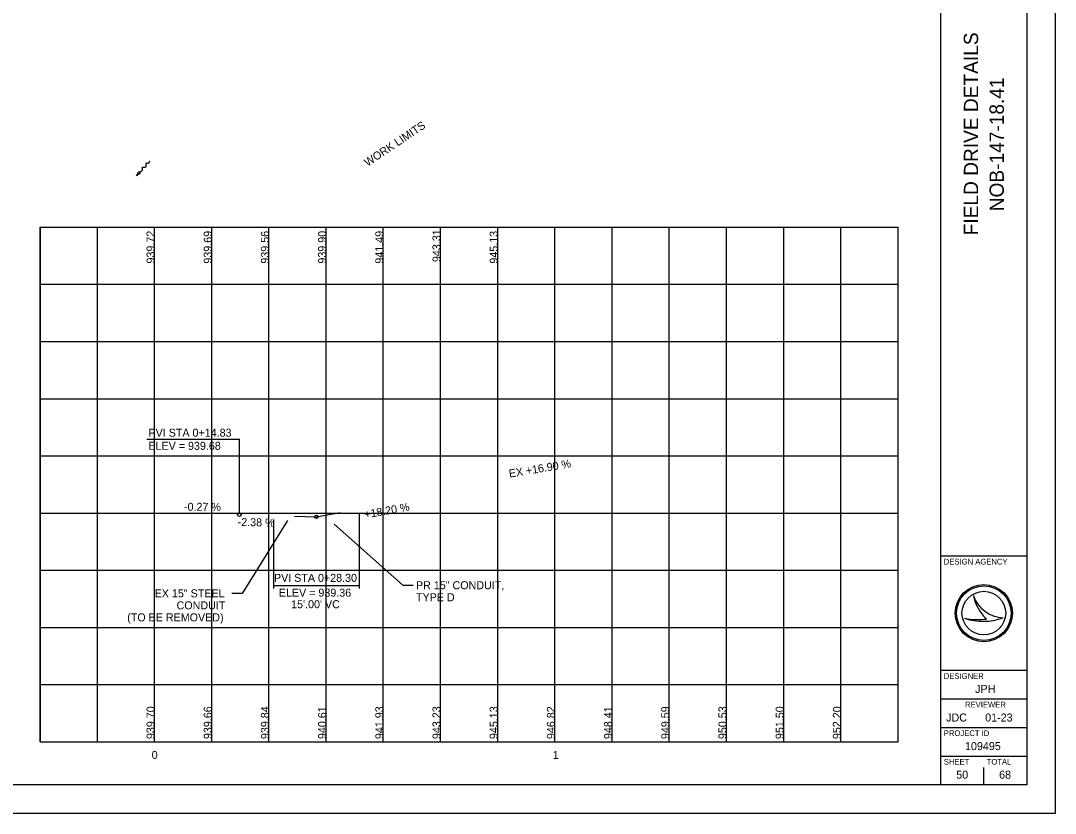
# Model space of a CAD drawing. Extents: x 1052 to 3483, y 402 to 622.
# Drawn here: x 1210.8 to 1391.7, y 401.8 to 540.4 of the extents above; entities that cross this region are included whole.
import ezdxf

# ---------------------------------------------------------------- set-up
doc = ezdxf.new("R2010")
doc.units = 0
for name, color, linetype in [('DR_P_Culvert', 7, 'Continuous'), ('DR_X_Culvert', 7, 'Continuous'), ('PF_X_Ground_Line', 7, 'Continuous'), ('RW_X_CL_100_Stations', 7, 'Continuous'), ('SC_Scratch1', 7, 'Continuous'), ('SV_X_Shot_Marker', 7, 'Continuous'), ('TX_P_1', 7, 'Continuous'), ('XS_X_Pavt', 7, 'Continuous')]:
    doc.layers.add(name, color=color, linetype=linetype)

msp = doc.modelspace()

# ---------------------------------------------------------------- linework, layer by layer
at = {"layer": 'DR_P_Culvert'}
for p, q in [((1257.45, 453.01), (1249.54, 440.25)), ((1249.54, 440.25), (1247.77, 440.25))]:
    msp.add_line(p, q, dxfattribs=at)
at = {"layer": 'DR_X_Culvert'}
for p, q in [((1214.23, 414.29), (1214.23, 504.29)), ((1224.23, 414.29), (1224.23, 504.29)), ((1234.23, 414.29), (1234.23, 504.29)), ((1244.23, 414.29), (1244.23, 504.29)), ((1254.23, 414.29), (1254.23, 504.29)), ((1264.23, 414.29), (1264.23, 504.29)), ((1274.23, 414.29), (1274.23, 504.29)), ((1284.23, 414.29), (1284.23, 504.29)), ((1294.23, 414.29), (1294.23, 504.29)), ((1304.23, 414.29), (1304.23, 504.29)), ((1314.23, 414.29), (1314.23, 504.29)), ((1324.23, 414.29), (1324.23, 504.29)), ((1334.23, 414.29), (1334.23, 504.29)), ((1344.23, 414.29), (1344.23, 504.29)), ((1354.23, 414.29), (1354.23, 504.29)), ((1214.23, 494.29), (1364.23, 494.29)), ((1214.23, 484.29), (1364.23, 484.29)), ((1214.23, 474.29), (1364.23, 474.29)), ((1214.23, 464.29), (1364.23, 464.29)), ((1214.23, 454.29), (1364.23, 454.29)), ((1214.23, 444.29), (1364.23, 444.29)), ((1214.23, 434.29), (1364.23, 434.29)), ((1214.23, 424.29), (1364.23, 424.29))]:
    msp.add_line(p, q, dxfattribs=at)
at = {"layer": 'PF_X_Ground_Line'}
for p, q in [((1232.86, 467.21), (1249.06, 467.21)), ((1249.06, 454.27), (1249.06, 467.21)), ((1262.52, 453.64), (1266.7, 454.4)), ((1270.02, 454.1), (1270.02, 441.07)), ((1255.02, 453.18), (1255.02, 441.07)), ((1258.69, 453.74), (1262.52, 453.64)), ((1255.02, 441.64), (1270.02, 441.64))]:
    msp.add_line(p, q, dxfattribs=at)
for centre in [(1249.06, 453.97), (1262.52, 453.64)]:
    msp.add_circle(centre, 0.3, dxfattribs=at)
at = {"layer": 'RW_X_CL_100_Stations'}
for p, q in [((1214.23, 504.29), (1364.23, 504.29)), ((1214.23, 504.29), (1214.23, 414.29)), ((1364.23, 414.29), (1364.23, 504.29)), ((1377.4, 439.88), (1377.4, 439.88)), ((1379.23, 436.79), (1379.23, 436.79)), ((1382.6, 435.97), (1382.6, 435.97)), ((1375.9, 435.88), (1375.9, 435.88)), ((1214.23, 414.29), (1364.23, 414.29)), ((1379.23, 406.79), (1379.23, 409.79)), ((1375.48, 408.54), (1375.48, 408.54))]:
    msp.add_line(p, q, dxfattribs=at)
for radius in [5, 4.77, 4.77, 3.82]:
    msp.add_circle((1379.23, 436.79), radius, dxfattribs=at)
for centre, radius, start, end in [((1382.88, 441.76), 5.8, 198.9257, 198.9319), ((1385.19, 441.49), 7.96, 191.6379, 191.6421), ((1382.88, 441.76), 5.8, 198.9319, 267.1657), ((1385.19, 441.49), 7.96, 191.6421, 226.0947), ((1379.12, 445.49), 10.13, 251.4576, 290.0832), ((1378.21, 448.33), 12.66, 259.4964, 259.4995), ((1379.12, 445.49), 10.13, 251.4527, 251.4576), ((1378.21, 448.33), 12.66, 259.4995, 276.6672)]:
    msp.add_arc(centre, radius, start, end, dxfattribs=at)
at = {"layer": 'SC_Scratch1'}
msp.add_lwpolyline([(1051.73, 401.79), (1391.73, 401.79), (1391.73, 621.79), (1051.73, 621.79)], close=True, dxfattribs=at)
at = {"layer": 'SV_X_Shot_Marker'}
for p, q in [((1371.73, 406.79), (1371.73, 616.79)), ((1371.73, 446.79), (1386.73, 446.79)), ((1371.73, 426.79), (1386.73, 426.79)), ((1371.73, 421.79), (1386.73, 421.79)), ((1371.73, 416.79), (1386.73, 416.79)), ((1371.73, 411.79), (1386.73, 411.79))]:
    msp.add_line(p, q, dxfattribs=at)
msp.add_lwpolyline([(1066.73, 616.79), (1386.73, 616.79), (1386.73, 406.79), (1066.73, 406.79)], close=True, dxfattribs=at)
at = {"layer": 'TX_P_1'}
for p, q in [((1265.64, 452.33), (1277.62, 441.67)), ((1277.62, 441.67), (1279.44, 441.67))]:
    msp.add_line(p, q, dxfattribs=at)
at = {"layer": 'XS_X_Pavt'}
for p, q in [((1231.09, 513.27), (1231.46, 514.01)), ((1231.46, 514.01), (1231.78, 513.73)), ((1231.78, 513.73), (1231.09, 513.27))]:
    msp.add_line(p, q, dxfattribs=at)
msp.add_spline([(1231.62, 513.87), (1231.64, 513.89), (1231.91, 514.09), (1232.11, 514.19), (1232.11, 514.76), (1232.74, 514.84), (1232.81, 515.54), (1233.05, 515.47), (1233.41, 515.89)], degree=3, dxfattribs=at)

# ---------------------------------------------------------------- texts
at = {"layer": 'DR_P_Culvert'}
for s, rotation, p in [('EX +16.90 %', 9.578, (1296.3, 460.48)), ('939.70', 90, (1234.23, 414.77)), ('939.66', 90, (1244.23, 414.77)), ('939.84', 90, (1254.23, 414.77)), ('940.61', 90, (1264.23, 414.77)), ('941.93', 90, (1274.23, 414.77)), ('943.23', 90, (1284.23, 414.77)), ('945.13', 90, (1294.23, 414.77)), ('946.82', 90, (1304.23, 414.77)), ('948.41', 90, (1314.23, 414.77)), ('949.59', 90, (1324.23, 414.77)), ('950.53', 90, (1334.23, 414.77)), ('951.50', 90, (1344.23, 414.77)), ('952.20', 90, (1354.23, 414.77))]:
    msp.add_text(s, height=1.4, rotation=rotation, dxfattribs=at).set_placement(p)
for s, p in [('EX 15" STEEL', (1234.25, 439.55)), ('CONDUIT', (1238.08, 437.45)), ('(TO BE REMOVED)', (1229.45, 435.35))]:
    msp.add_text(s, height=1.4, dxfattribs=at).set_placement(p)
at = {"layer": 'PF_X_Ground_Line'}
for s, p in [('PVI STA 0+14.83', (1233.17, 467.64)), ('ELEV = 939.68', (1233.16, 465.35)), ('PVI STA 0+28.30', (1255.11, 442.26)), ('ELEV = 939.36', (1255.96, 439.67)), ("15'.00' VC", (1258.11, 437.65))]:
    msp.add_text(s, height=1.4, dxfattribs=at).set_placement(p)
for s, rotation, p in [('+18.20 %', 10.3207, (1271.06, 453.32)), ('-2.38 %', 358.6373, (1248.75, 452.05))]:
    msp.add_text(s, height=1.4, rotation=rotation, dxfattribs=at).set_placement(p)
at = {"layer": 'RW_X_CL_100_Stations'}
for s, p in [('FIELD DRIVE DETAILS', (1378.23, 502.86)), ('NOB-147-18.41', (1382.73, 507.06))]:
    msp.add_text(s, height=2.5, rotation=90, dxfattribs=at).set_placement(p)
for s, height, p in [('DESIGN AGENCY', 1, (1372.23, 445.29)), ('DESIGNER', 1, (1372.23, 425.29)), ('JPH', 1.4, (1377.71, 422.84)), ('REVIEWER', 1, (1375.94, 420.29)), ('JDC', 1.4, (1372.64, 417.84)), ('01-23', 1.4, (1379.47, 417.84)), ('PROJECT ID', 1, (1372.23, 415.29)), ('109495', 1.4, (1375.94, 412.84)), ('SHEET', 1, (1372.23, 410.29)), ('TOTAL', 1, (1379.73, 410.29)), ('50', 1.4, (1374.4, 407.84)), ('68', 1.4, (1381.9, 407.84))]:
    msp.add_text(s, height=height, dxfattribs=at).set_placement(p)
at = {"layer": 'TX_P_1'}
for s, rotation, p in [('WORK LIMITS', 33.8644, (1271.47, 514.85)), ('939.72', 90, (1234.23, 497.93)), ('939.69', 90, (1244.23, 497.91)), ('939.56', 90, (1254.23, 497.91)), ('939.90', 90, (1264.23, 497.92)), ('941.49', 90, (1274.23, 497.91)), ('943.31', 90, (1284.23, 498.18)), ('945.13', 90, (1294.23, 497.91)), ('-0.27 %', 359.8416, (1239.38, 454.69))]:
    msp.add_text(s, height=1.4, rotation=rotation, dxfattribs=at).set_placement(p)
for s, p in [('PR 15" CONDUIT,', (1279.94, 440.97)), ('TYPE D', (1279.94, 438.87)), ('0', (1233.73, 411.3)), ('1', (1303.86, 411.3))]:
    msp.add_text(s, height=1.4, dxfattribs=at).set_placement(p)

doc.saveas('drawing.dxf')
